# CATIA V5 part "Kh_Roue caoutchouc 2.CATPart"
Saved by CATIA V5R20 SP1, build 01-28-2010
Part number: Roue caoutchouc 2
Bounding box of the stored display mesh (mm): x -55.995 to 55.995, y -29 to 29, z -55.995 to 55.995
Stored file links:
  G:\Khaled_CFAO_2011\SIL\SIL_GR1\tmerino\Khaled\CAD_Thinkmotion\Kh_Roue caoutchouc 2.CATPart
  G:\Khaled_CFAO_2011\SIL\SIL_GR1\tmerino\Khaled\CAD_Thinkmotion\Kh_Catalog.CATMaterial
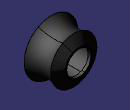
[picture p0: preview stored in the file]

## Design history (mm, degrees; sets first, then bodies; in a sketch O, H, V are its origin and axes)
Body1 (main body), material "Caoutchouc"
  Sketch1 on yz-plane, origin (0, 0, 0), H (0, 1, 0), V (0, 0, 1)
    line L1 (-29, -56) -> (-29, -42)
    point P3 (29, 90)
    line L2 (-29, -42) -> (-23, -42)
    line L3 (-23, -42) -> (-23, -34)
    line L4 (-23, -34) -> (23, -34)
    line L5 (23, -34) -> (23, -25)
    line L6 (23, -25) -> (29, -25)
    line L7 (29, -25) -> (29, -56)
    arc A1 centre (0, -83.55) radius 40 from (29, -56) to (-29, -56) ccw
    distance V L1 = 29
    length L1 = 14
    length L2 = 6
    length L3 = 8
    length L4 = 46
    length L5 = 9
    length L6 = 6
    vertical: L1 V, L3 V, L5 V, L7 V
    horizontal: L2 H, L4 H, L6 H
    fix: A1
  Shaft1: profile Sketch1, axis Sketch1.H, angle 360
  Sketch2 on face of Shaft1 from Sketch1.L3, origin (11.6205, -23, -36.2849), H (1, 0, 0), V (0, 0, 1)
    point P1 (26.3795, 36.2849)
    reference intersected line E1 through (0, 36.2849) direction (-1, 0) from xy-plane
    reference intersected line E2 through (-11.6205, 0) direction (0, 1) from yz-plane
    distance E1 P1 = 0
    distance E2 P1 = 38
  Hole1: placed by Sketch2, at (38, -23, 0) direction (0, 1, 0), diameter 3.5, depth 10, threaded, thread diameter 4, thread depth 10, pitch 1
  CircPattern1: of Hole1, instances 9, angular step 40, axis from face of Shaft1 from Sketch1.L4
  Chamfer1: length 12, angle 89, on edge [face of Shaft1 from Sketch1.A1 | face of Shaft1 from Sketch1.L7]
  Sketch3 on zx-plane, origin (0, 0, 0), H (-1, 0, 0), V (0, 0, 1)
    circle A1 centre (0, 0) radius 43.55
    radius A1 = 43.55
  Sketch4 on face of Shaft1 from Sketch1.L1, origin (0, -29, 0), H (1, 0, 0), V (0, 0, 1)
    point P1 (56, 0)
